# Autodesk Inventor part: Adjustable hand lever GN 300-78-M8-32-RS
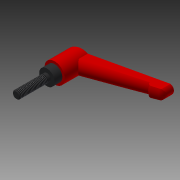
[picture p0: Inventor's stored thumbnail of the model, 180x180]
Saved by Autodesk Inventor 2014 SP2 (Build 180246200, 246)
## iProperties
Created: 2019-10
Part Number: Adjustable hand lever GN 300-78-M8-32-RS
Material: Generic
Catalog Web Link: www.cadenas.de
Description: GN 300-Adjustable hand levers with male thread
Vendor: GANTER
Document SubType Name: Modeling
Designer: psadmin
Manufacturer: GANTER
Mass: 136 g
Surface Area: 66.1981 cm^2
Volume: 21.083 cm^3
Density: 1 g/cm^3
Appearance: PSOLRGB-255-0-0
Category: PARTsolutions
Company: GANTER
Title: Adjustable hand lever GN 300-78-M8-32-RS
Author: Cadenas PARTsolutions
Comments: Adjustable hand levers with male thread
PSOL_IDENT_0: {$CADENAS_DATA\23d-libs\ganter\data\2_1\gn_300\gn_300_ms\gn300_ms.prj},224 {VTYP=3D},{NB=Adjustable
PSOL_IDENT_1: hand lever GN 300-78-M8-32-RS},{LINA=Adjustable hand lever GN 300-78-M8-32-RS},{NN=GN 300},{DATE=08.
PSOL_IDENT_2: 10.2019 15:17:01},{GEOMDATE=24.09.2019 13:55:25},{VERSION=v1},{LINEID=5420},{WBVAR=},{WBNUMERIC=}  {
PSOL_IDENT_3: NB=Verstellbarer Klemmhebel GN 300-78-M8-32-RS},{LINA=Verstellbarer Klemmhebel GN 300-78-M8-32-RS},{
PSOL_IDENT_4: KT=DUMMY},{PARTNUMBER=GN 300-78-M8-32-RS},{NORMNR=GN 300},{L1=78},{L=13.000},{D1=M8},{D1Y=8},{D1X=8,
PSOL_IDENT_5: 10},{L2=32},{L2X=16,20,25,32,40,50,63,80},{FARBE=rot (strukturmatt)},{VER=4},{AUSWAHL= 'SW', 'schwar
PSOL_IDENT_6: z (strukturmatt)', 'SZ', 'schwarz (seidenglanz)', 'OR'  , 'orange', 'RS', 'rot (strukturmatt)', 'SB'
PSOL_IDENT_7: , 'silber', 'CR', 'verchromt', 'RH'  , 'unlackiert'},{D3=16.0},{D4=21.0},{H1=36.0},{H2=8.0},{H3=54},
PSOL_IDENT_8: {H4=4.0},{T=14},{ABS1=3.000},{R1=4.000},{R2=6.000},{R3=3.000},{ABS2=15.000},{R4=3.000},{R5=3.000},{R
PSOL_IDENT_9: 6=6.000},{ABS3=22.000},{ABS4=14.000},{ABS5=6.500},{SW=5.000},{VERS=2},{FARBER=1},{FARBEG=0},{FARBEB=
PSOL_IDENT_10: 0},{FARBEX=RS},{WEIGHT=0.1360},{CTN=84879090},{ROHS=YES},{INFOGANTER=Produktdetails},{INFOGANTERX=ht
PSOL_IDENT_11: tps://www.ganternorm.com/en/products/2.1-Tensioning-clamping-switching-with-levers/GN-300-Adjustable
PSOL_IDENT_12: -hand-levers-Zinc-die-casting-with-threaded-stud},{TT=25.000},{AA=4.430},{LL=2.000},{DIST=5.28}
NN: GN 300
NT: Adjustable hand levers with male thread
NB: Adjustable hand lever GN 300-78-M8-32-RS
NBSYN: Adjustable hand lever $PARTNUMBER.
LINA: Adjustable hand lever GN 300-78-M8-32-RS
PARTNUMBER: GN 300-78-M8-32-RS
L1: 78
D1: M8
L2: 32
FARBE: red (textured finish)
D3: 16
D4: 21
H1: 36
H2: 8
H3: 54
H4: 4
WEIGHT: 0.136
CTN: 84879090
ROHS: YES
INFOGANTER: Product details
SUPPLIER: GANTER
ARTICLENO: Adjustable hand lever GN 300-78-M8-32-RS
BOMINFO: Adjustable hand lever GN 300-78-M8-32-RS
CREATOR: CADENAS GmbH
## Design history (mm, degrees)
sketch "Sketch_1"
  geometry: L1 (0, 18.178)-(0, 33.1); L2 (0, 33.1)-(79, 54.268); L3 (79, 54.268)-(79, 43.739); L4 (79, 43.739)-(67.844, 39.679); L5 (63.999, 41.472)-(0, 18.178); L6 (0, 18.178)-(0, 33.1); A1 r 3 centre (66.818, 42.498) between (63.999, 41.472) and (67.844, 39.679)
  constraints: 12 end point, 2 point on circle, 1 centre point
sketch "Sketch_2"
  geometry: L1 (156, 156)-(-156, 156); L2 (-156, 156)-(-156, -156); L3 (-156, -156)-(156, -156); L4 (156, -156)-(156, 156); L5 (-7.348, -7.5)-(-7.348, 7.5); L6 (-7.348, 7.5)-(-75.107, 5.134); L7 (-75.107, -5.134)-(-7.348, -7.5); A1 r 6.001 centre (-72, 0) between (-75.107, 5.134) and (-75.107, -5.134)
  constraints: 14 end point, 2 point on circle, 1 centre point
revolve "Revolution1" stored, may be unused: angle "d0" = 360 deg
extrude "Extrusion1" cut sketch "Sketch_2" distance "d1" = 58; taper "d2" = 0 deg
sketch "Sketch_3"
  geometry: L1 (-11.5, 30.019)-(78, 54); L2 (78, 54)-(78, 58); L3 (78, 58)-(-11.5, 58); L4 (-11.5, 58)-(-11.5, 30.019)
  constraints: 8 end point
sketch "Sketch_15"
  geometry: L1 (-2.839, 25.978)-(61.16, 49.271); L2 (0, 18.178)-(0, 7.537); L3 (0, 7.537)-(79, 36.29); L4 (79, 36.29)-(79, 47.576); L5 (79, 47.576)-(77.999, 47.576); L6 (74.051, 41.938)-(67.844, 39.679); L7 (63.999, 41.472)-(0, 18.178); A1 r 6 centre (71.999, 47.576) between (74.051, 41.938) and (77.999, 47.576); A2 r 3 centre (66.818, 42.498) between (63.999, 41.472) and (67.844, 39.679)
  constraints: 14 end point, 4 point on circle, 2 centre point
revolve "Revolution2" sketch "Sketch_15" stored, may be unused: angle "d3" = 180 deg
sketch "Sketch_20"
  geometry: L1 (0, 0)-(0, 33.1); L2 (0, 33.1)-(10.5, 35.913); L3 (10.5, 35.913)-(10.5, 8); L4 (10.5, 8)-(8, 8); L5 (8, 8)-(8, 0); L6 (8, 0)-(0, 0); L7 (0, 0)-(0, 33.1)
  constraints: 14 end point
revolve "Revolution3" sketch "Sketch_20" stored, may be unused: angle "d4" = 360 deg
extrude "Extrusion2" cut sketch "Sketch_3" stored distance "d5" = 23; taper "d6" = 0 deg
sketch "Sketch_4"
  geometry: L1 (0, 20.153)-(0, 36); L2 (0, 36)-(5, 36); L3 (6.5, 34.5)-(6.5, 20.153); L4 (6.5, 20.153)-(0, 20.153); L5 (0, 20.153)-(0, 36); A1 r 1.5 centre (5, 34.5) between (6.5, 34.5) and (5, 36)
  constraints: 10 end point, 2 point on circle, 1 centre point
revolve "Revolution4" sketch "Sketch_4" stored, may be unused: angle "d7" = 360 deg
sketch "Sketch7"
  geometry: 1 further point
hole "Hole1" sketch "Sketch7" at (0, 0) diameter "d8" = 4.43; stored, may be unused: countersink angle "d12" = 90 deg, drill point angle "d14" = 120 deg; dims "d9" = 6, "d10" = 4, "d11" = 2, "d13" = 2
sketch "Sketch_10"
  geometry: C1 r 2.658 at (0, 0); A1 r 0.443 centre (-1.535, -0.886) between (-1.839, -0.564) and (-1.408, -1.31); A2 r 0.775 centre (-1.185, -2.053) between (-0.431, -1.874) and (-1.408, -1.31); A3 r 0.443 centre (0, -1.772) between (-0.431, -1.874) and (0.431, -1.874); A4 r 0.775 centre (1.185, -2.053) between (1.408, -1.31) and (0.431, -1.874); A5 r 0.443 centre (1.535, -0.886) between (1.408, -1.31) and (1.839, -0.564); A6 r 0.775 centre (2.371, 0) between (1.839, 0.564) and (1.839, -0.564); A7 r 0.443 centre (1.535, 0.886) between (1.839, 0.564) and (1.408, 1.31); A8 r 0.775 centre (1.185, 2.053) between (0.431, 1.874) and (1.408, 1.31); A9 r 0.443 centre (0, 1.772) between (0.431, 1.874) and (-0.431, 1.874); A10 r 0.775 centre (-1.185, 2.053) between (-1.408, 1.31) and (-0.431, 1.874); A11 r 0.443 centre (-1.535, 0.886) between (-1.408, 1.31) and (-1.839, 0.564); A12 r 0.775 centre (-2.371, 0) between (-1.839, -0.564) and (-1.839, 0.564); 1 further point
  constraints: 24 point on circle, 13 centre point
extrude "Extrusion3" join sketch "Sketch_10" distance "d15" = 4; taper "d16" = 0 deg
sketch "Sketch_11"
  geometry: L1 (0, 34.721)-(0, 36); L2 (0, 36)-(2.215, 36); L3 (2.215, 36)-(0, 34.721); L4 (0, 34.721)-(0, 36)
  constraints: 8 end point
revolve "Revolution5" sketch "Sketch_11" stored, may be unused: angle "d17" = 360 deg
sketch "Sketch_6"
  geometry: L1 (0, -32)-(0, 0); L2 (0, 0)-(4, 0); L3 (4, 0)-(4, -31.233); L4 (4, -31.233)-(3.233, -32); L5 (3.233, -32)-(0, -32); L6 (0, -32)-(0, 0)
  constraints: 12 end point
revolve "Revolution6" sketch "Sketch_6" stored, may be unused: angle "d18" = 360 deg
thread "Thread1" dims "d19" = 28.033, "d20" = 0
node "T_XY"
node "T_YZ"
node "T_ZX"
node "T_X"
node "T_Y"
node "T_Z"
node "T_Center"
body "Solid1"
other parameters: "d21" = 0
